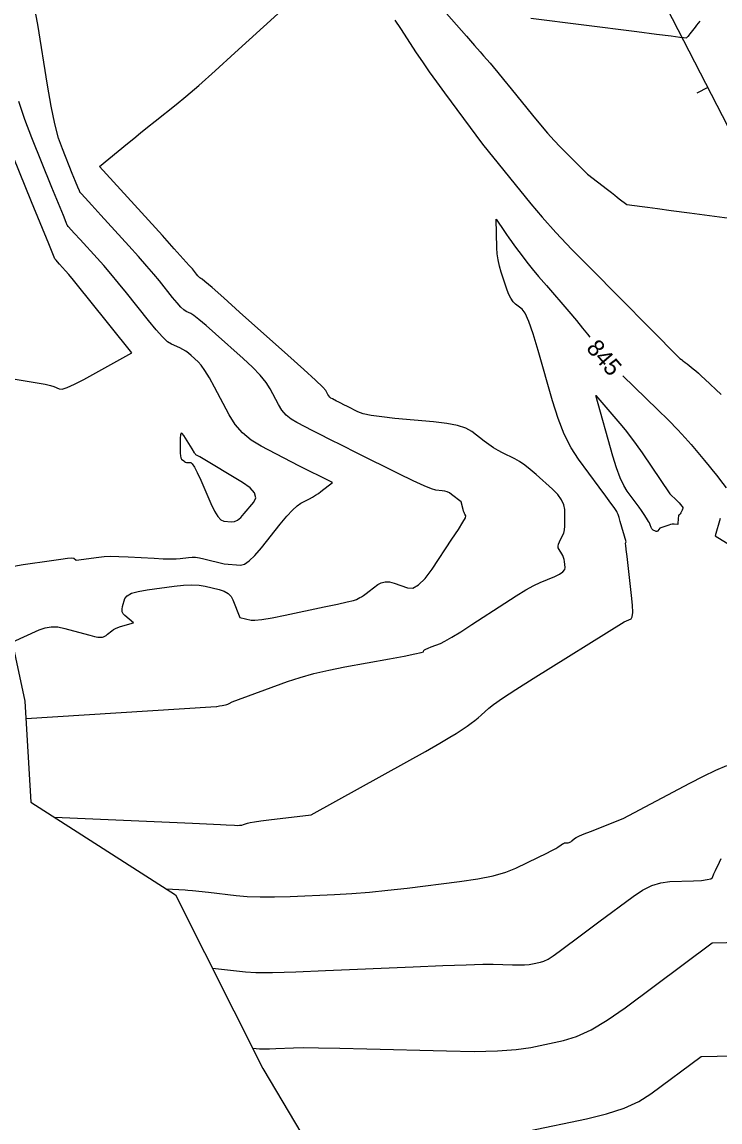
# Model space of a CAD drawing. Extents: x 1715724 to 1716561, y 394063 to 395906.
# Drawn here: x 1715878.2 to 1715935.5, y 395212.3 to 395302.7 of the extents above; entities that cross this region are included whole.
import ezdxf

# ---------------------------------------------------------------- set-up
doc = ezdxf.new("R2010")
doc.units = 0
for name, color, linetype in [('DT_X_Contour_Major', 7, 'Continuous'), ('DT_X_Contour_Minor', 7, 'Continuous'), ('DT_X_TIN_Hull', 7, 'Continuous'), ('GE_P_CL_10', 7, 'Continuous')]:
    doc.layers.add(name, color=color, linetype=linetype)

msp = doc.modelspace()

# ---------------------------------------------------------------- linework, layer by layer
at = {"layer": 'DT_X_Contour_Major'}
for points in [[(1715880.835, 395237.361), (1715892.192, 395236.859), (1715894.484, 395236.754), (1715894.957, 395236.73), (1715895.619, 395236.69), (1715895.852, 395236.683), (1715896.055, 395236.69), (1715896.228, 395236.712), (1715896.37, 395236.748), (1715896.708, 395236.865), (1715896.913, 395236.915), (1715897.271, 395236.976), (1715897.784, 395237.05), (1715898.451, 395237.136), (1715901.926, 395237.565), (1715909.789, 395241.915), (1715911.306, 395242.76), (1715912.486, 395243.428), (1715913.33, 395243.921), (1715913.837, 395244.237), (1715914.74, 395244.847), (1715915.065, 395245.074), (1715915.365, 395245.298), (1715915.638, 395245.519), (1715915.884, 395245.737), (1715916.508, 395246.314), (1715916.912, 395246.629), (1715917.657, 395247.139), (1715918.744, 395247.846), (1715920.171, 395248.748), (1715927.628, 395253.418), (1715928.208, 395253.659), (1715928.303, 395253.817), (1715928.341, 395254.189), (1715928.322, 395254.775), (1715928.245, 395255.575), (1715927.871, 395258.786), (1715927.804, 395259.354), (1715927.762, 395259.697), (1715927.746, 395259.815), (1715927.738, 395259.827), (1715927.737, 395259.834), (1715927.739, 395259.846), (1715927.755, 395259.882), (1715927.811, 395259.988), (1715927.317, 395261.653), (1715927.22, 395261.972), (1715927.139, 395262.218), (1715927.075, 395262.39), (1715927.027, 395262.487), (1715926.922, 395262.649), (1715926.809, 395262.81), (1715926.547, 395263.169), (1715926.137, 395263.728), (1715925.579, 395264.487), (1715923.891, 395266.775), (1715923.283, 395267.719), (1715922.722, 395268.835), (1715922.209, 395270.122), (1715921.744, 395271.581), (1715920.568, 395275.699), (1715920.156, 395277.07), (1715919.802, 395278.094), (1715919.507, 395278.771), (1715919.269, 395279.1), (1715918.713, 395279.516), (1715918.511, 395279.714), (1715918.319, 395279.998), (1715918.138, 395280.367), (1715917.968, 395280.821), (1715917.53, 395282.146), (1715917.385, 395282.643), (1715917.279, 395283.142), (1715917.211, 395283.643), (1715917.182, 395284.146), (1715917.135, 395286.495), (1715917.812, 395285.47), (1715917.972, 395285.234), (1715918.162, 395284.962), (1715918.381, 395284.657), (1715918.631, 395284.316), (1715919.337, 395283.363), (1715919.655, 395282.95), (1715920.079, 395282.426), (1715920.609, 395281.791), (1715921.246, 395281.044), (1715923.086, 395278.905), (1715923.716, 395278.165), (1715924.226, 395277.549), (1715924.616, 395277.056), (1715924.805, 395276.798)], [(1715927.533, 395273.63), (1715930.377, 395270.856), (1715931.274, 395269.969), (1715932.032, 395269.194), (1715932.652, 395268.531), (1715933.133, 395267.98), (1715934.23, 395266.659), (1715934.616, 395266.192), (1715934.952, 395265.781), (1715935.236, 395265.428), (1715935.47, 395265.131), (1715936.025, 395264.415)], [(1715935.525, 395261.909), (1715935.121, 395260.478), (1715936.766, 395259.454)]]:
    msp.add_lwpolyline(points, dxfattribs=at)
at = {"layer": 'DT_X_Contour_Minor'}
for points in [[(1715911.397, 395305.284), (1715913.854, 395302.472), (1715914.685, 395301.521), (1715915.335, 395300.777), (1715915.804, 395300.24), (1715916.093, 395299.91), (1715916.621, 395299.306), (1715916.877, 395299.006), (1715917.25, 395298.557), (1715917.739, 395297.96), (1715918.344, 395297.214), (1715920.114, 395295.029), (1715920.754, 395294.252), (1715921.348, 395293.56), (1715921.894, 395292.953), (1715922.394, 395292.432), (1715924.616, 395290.198), (1715926.262, 395288.929), (1715926.587, 395288.679), (1715926.857, 395288.47), (1715927.072, 395288.304), (1715927.233, 395288.18), (1715927.853, 395287.699), (1715929.12, 395287.537), (1715929.566, 395287.478), (1715930.363, 395287.372), (1715931.511, 395287.219), (1715933.008, 395287.019), (1715940.815, 395285.973)], [(1715878.507, 395245.476), (1715893.7, 395246.43), (1715894.141, 395246.451), (1715894.157, 395246.453), (1715894.192, 395246.459), (1715894.402, 395246.506), (1715894.631, 395246.549), (1715894.903, 395246.596), (1715894.998, 395246.615), (1715895.08, 395246.637), (1715895.149, 395246.662), (1715895.205, 395246.69), (1715895.434, 395246.825), (1715899.992, 395248.494), (1715901.018, 395248.838), (1715902.145, 395249.155), (1715903.37, 395249.446), (1715904.696, 395249.709), (1715908.363, 395250.375), (1715909.569, 395250.598), (1715910.434, 395250.769), (1715910.959, 395250.887), (1715911.144, 395250.953), (1715911.184, 395251.058), (1715911.233, 395251.106), (1715911.349, 395251.171), (1715911.532, 395251.254), (1715911.783, 395251.354), (1715912.541, 395251.643), (1715912.917, 395251.821), (1715913.474, 395252.137), (1715914.213, 395252.592), (1715915.133, 395253.186), (1715917.83, 395254.953), (1715918.771, 395255.556), (1715919.571, 395256.04), (1715920.229, 395256.405), (1715920.747, 395256.65), (1715921.938, 395257.146), (1715922.326, 395257.331), (1715922.597, 395257.516), (1715922.752, 395257.699), (1715922.789, 395257.882), (1715922.732, 395258.369), (1715922.703, 395258.545), (1715922.657, 395258.707), (1715922.595, 395258.857), (1715922.517, 395258.994), (1715922.286, 395259.342), (1715922.223, 395259.48), (1715922.207, 395259.634), (1715922.237, 395259.802), (1715922.314, 395259.985), (1715922.583, 395260.494), (1715922.67, 395260.708), (1715922.731, 395260.97), (1715922.765, 395261.279), (1715922.773, 395261.635), (1715922.757, 395262.648), (1715922.689, 395263.037), (1715922.498, 395263.444), (1715922.184, 395263.87), (1715921.746, 395264.313), (1715920.413, 395265.521), (1715919.929, 395265.94), (1715919.475, 395266.293), (1715919.052, 395266.578), (1715918.659, 395266.797), (1715917.653, 395267.292), (1715917.275, 395267.491), (1715916.896, 395267.717), (1715916.516, 395267.971), (1715916.134, 395268.252), (1715915.115, 395269.038), (1715914.631, 395269.31), (1715913.947, 395269.534), (1715913.06, 395269.712), (1715911.973, 395269.842), (1715908.803, 395270.129), (1715907.722, 395270.243), (1715906.857, 395270.37), (1715906.207, 395270.512), (1715905.773, 395270.667), (1715904.904, 395271.099), (1715904.603, 395271.249), (1715904.353, 395271.374), (1715904.153, 395271.474), (1715904.004, 395271.55), (1715903.674, 395271.72), (1715903.557, 395271.791), (1715903.456, 395271.877), (1715903.369, 395271.977), (1715903.298, 395272.091), (1715903.127, 395272.415), (1715902.885, 395272.687), (1715902.287, 395273.262), (1715901.332, 395274.139), (1715900.022, 395275.318), (1715896.052, 395278.865), (1715894.744, 395280.032), (1715893.796, 395280.871), (1715893.208, 395281.383), (1715892.98, 395281.568), (1715892.854, 395281.625), (1715892.796, 395281.663), (1715892.719, 395281.736), (1715892.623, 395281.842), (1715892.506, 395281.983), (1715892.169, 395282.404), (1715891.921, 395282.694), (1715891.427, 395283.249), (1715890.688, 395284.069), (1715889.705, 395285.153), (1715884.543, 395290.831), (1715886.841, 395292.717), (1715887.352, 395293.135), (1715887.902, 395293.58), (1715888.49, 395294.052), (1715889.117, 395294.551), (1715890.838, 395295.92), (1715891.624, 395296.57), (1715892.69, 395297.492), (1715894.037, 395298.689), (1715895.664, 395300.158), (1715900.376, 395304.441)], [(1715877.367, 395251.733), (1715879.583, 395252.758), (1715880.07, 395252.93), (1715880.584, 395253.007), (1715881.124, 395252.989), (1715881.69, 395252.875), (1715883.235, 395252.445), (1715883.752, 395252.304), (1715884.146, 395252.207), (1715884.414, 395252.151), (1715884.559, 395252.138), (1715884.779, 395252.159), (1715884.868, 395252.179), (1715884.968, 395252.224), (1715885.08, 395252.294), (1715885.204, 395252.39), (1715885.55, 395252.677), (1715885.692, 395252.779), (1715885.859, 395252.87), (1715886.051, 395252.951), (1715886.268, 395253.02), (1715887.336, 395253.321), (1715886.613, 395253.927), (1715886.487, 395254.072), (1715886.417, 395254.245), (1715886.403, 395254.446), (1715886.446, 395254.676), (1715886.637, 395255.329), (1715886.803, 395255.557), (1715887.16, 395255.752), (1715887.708, 395255.914), (1715888.446, 395256.043), (1715890.669, 395256.343), (1715891.453, 395256.427), (1715892.139, 395256.456), (1715892.725, 395256.43), (1715893.214, 395256.347), (1715894.384, 395256.054), (1715894.783, 395255.918), (1715895.104, 395255.732), (1715895.345, 395255.496), (1715895.508, 395255.209), (1715896.082, 395253.753), (1715896.992, 395253.547), (1715897.313, 395253.54), (1715897.887, 395253.607), (1715898.714, 395253.748), (1715899.794, 395253.963), (1715903.01, 395254.635), (1715904.08, 395254.863), (1715904.875, 395255.041), (1715905.396, 395255.17), (1715905.643, 395255.25), (1715905.936, 395255.399), (1715906.066, 395255.473), (1715906.234, 395255.584), (1715906.441, 395255.733), (1715906.686, 395255.919), (1715907.392, 395256.465), (1715907.676, 395256.626), (1715907.995, 395256.7), (1715908.351, 395256.686), (1715908.743, 395256.585), (1715909.837, 395256.201), (1715910.272, 395256.189), (1715910.756, 395256.443), (1715911.29, 395256.962), (1715911.873, 395257.746), (1715913.493, 395260.191), (1715914.021, 395261), (1715914.388, 395261.592), (1715914.595, 395261.967), (1715914.642, 395262.126), (1715914.552, 395262.261), (1715914.519, 395262.322), (1715914.485, 395262.403), (1715914.452, 395262.506), (1715914.418, 395262.63), (1715914.262, 395263.258), (1715913.455, 395263.88), (1715913.278, 395263.999), (1715913.094, 395264.089), (1715912.901, 395264.151), (1715912.701, 395264.183), (1715912.158, 395264.232), (1715911.816, 395264.33), (1715911.2, 395264.584), (1715910.308, 395264.996), (1715909.142, 395265.565), (1715905.665, 395267.292), (1715904.463, 395267.89), (1715903.462, 395268.391), (1715902.663, 395268.793), (1715902.067, 395269.097), (1715900.745, 395269.777), (1715900.279, 395270.061), (1715899.873, 395270.402), (1715899.527, 395270.802), (1715899.241, 395271.259), (1715898.558, 395272.555), (1715898.227, 395273.075), (1715897.747, 395273.665), (1715897.118, 395274.323), (1715896.34, 395275.05), (1715894.067, 395277.082), (1715893.302, 395277.757), (1715892.712, 395278.258), (1715892.298, 395278.587), (1715892.058, 395278.741), (1715891.653, 395278.923), (1715891.469, 395279.046), (1715891.223, 395279.278), (1715890.913, 395279.62), (1715890.541, 395280.07), (1715889.463, 395281.418), (1715889.003, 395281.978), (1715888.429, 395282.647), (1715887.741, 395283.426), (1715886.94, 395284.315), (1715884.653, 395286.831), (1715883.902, 395287.657), (1715883.365, 395288.248), (1715883.042, 395288.605), (1715882.933, 395288.727), (1715882.928, 395288.74), (1715882.888, 395288.838), (1715882.772, 395289.124), (1715882.579, 395289.596), (1715882.311, 395290.255), (1715881.492, 395292.262), (1715881.186, 395293.154), (1715880.881, 395294.325), (1715880.576, 395295.776), (1715880.273, 395297.504), (1715879.465, 395302.487), (1715879.157, 395304.187)], [(1715908.802, 395302.84), (1715909.257, 395302.151), (1715910.561, 395300.176), (1715911.072, 395299.416), (1715911.629, 395298.614), (1715912.231, 395297.771), (1715912.878, 395296.887), (1715916.003, 395292.666), (1715919.97, 395287.768), (1715920.911, 395286.651), (1715922.036, 395285.398), (1715923.344, 395284.01), (1715924.835, 395282.486), (1715932.221, 395275.06), (1715932.334, 395274.973), (1715932.356, 395274.956), (1715932.373, 395274.943), (1715932.386, 395274.932), (1715932.394, 395274.926), (1715932.409, 395274.912), (1715932.438, 395274.888), (1715932.514, 395274.828), (1715932.635, 395274.731), (1715932.804, 395274.598), (1715933.314, 395274.193), (1715933.518, 395274.027), (1715933.746, 395273.83), (1715933.997, 395273.603), (1715934.273, 395273.347), (1715935.617, 395272.081)], [(1715919.978, 395303.025), (1715928.666, 395301.91), (1715930.302, 395301.7), (1715931.486, 395301.548), (1715932.219, 395301.454), (1715932.499, 395301.418), (1715932.754, 395301.383), (1715932.872, 395301.501), (1715932.909, 395301.542), (1715932.97, 395301.617), (1715933.055, 395301.725), (1715933.164, 395301.865), (1715933.485, 395302.283), (1715933.608, 395302.443), (1715933.735, 395302.606), (1715933.868, 395302.774)], [(1715877.504, 395257.995), (1715878.277, 395258.108), (1715880.599, 395258.461), (1715881.366, 395258.571), (1715881.927, 395258.639), (1715882.281, 395258.665), (1715882.427, 395258.648), (1715882.63, 395258.469), (1715884.486, 395258.736), (1715884.935, 395258.78), (1715885.484, 395258.798), (1715886.135, 395258.79), (1715886.887, 395258.757), (1715889.027, 395258.633), (1715889.762, 395258.596), (1715890.363, 395258.581), (1715890.829, 395258.586), (1715891.161, 395258.611), (1715891.866, 395258.706), (1715892.142, 395258.726), (1715892.441, 395258.715), (1715892.763, 395258.672), (1715893.108, 395258.598), (1715894.772, 395258.181), (1715896.123, 395258.08), (1715896.448, 395258.152), (1715896.845, 395258.412), (1715897.313, 395258.859), (1715897.853, 395259.494), (1715899.388, 395261.436), (1715899.925, 395262.091), (1715900.386, 395262.597), (1715900.769, 395262.955), (1715901.076, 395263.164), (1715901.791, 395263.526), (1715902.051, 395263.664), (1715902.295, 395263.807), (1715902.523, 395263.957), (1715902.735, 395264.111), (1715903.686, 395264.846), (1715902.41, 395265.48), (1715902.063, 395265.655), (1715900.922, 395266.237), (1715897.816, 395267.834), (1715897.001, 395268.33), (1715896.291, 395268.928), (1715895.685, 395269.627), (1715895.184, 395270.427), (1715893.988, 395272.695), (1715893.569, 395273.463), (1715893.207, 395274.067), (1715892.904, 395274.507), (1715892.659, 395274.783), (1715892.082, 395275.298), (1715891.86, 395275.482), (1715891.629, 395275.646), (1715891.387, 395275.79), (1715891.136, 395275.915), (1715890.452, 395276.222), (1715890.142, 395276.429), (1715889.727, 395276.821), (1715889.204, 395277.397), (1715888.576, 395278.158), (1715886.758, 395280.431), (1715886.096, 395281.249), (1715885.474, 395281.997), (1715884.892, 395282.676), (1715884.35, 395283.285), (1715882.958, 395284.816), (1715882.5, 395285.32), (1715881.974, 395285.904), (1715881.906, 395285.984), (1715881.895, 395286.01), (1715881.813, 395286.21), (1715881.577, 395286.79), (1715880.64, 395289.09), (1715878.977, 395293.169), (1715878.403, 395294.683), (1715877.928, 395296.166)], [(1715875.273, 395273.734), (1715878.607, 395273.193), (1715879.436, 395273.053), (1715880.075, 395272.931), (1715880.525, 395272.828), (1715880.786, 395272.743), (1715881.228, 395272.542), (1715881.479, 395272.534), (1715881.9, 395272.663), (1715882.49, 395272.928), (1715883.25, 395273.329), (1715887.191, 395275.518), (1715883.65, 395279.947), (1715882.963, 395280.803), (1715882.419, 395281.473), (1715882.018, 395281.957), (1715881.76, 395282.255), (1715881.263, 395282.801), (1715881.099, 395282.983), (1715880.98, 395283.116), (1715880.906, 395283.203), (1715880.878, 395283.241), (1715880.382, 395284.457), (1715878.969, 395287.925), (1715876.461, 395294.077)], [(1715925.302, 395271.997), (1715927.278, 395269.701), (1715927.709, 395269.181), (1715928.158, 395268.605), (1715928.623, 395267.972), (1715929.105, 395267.284), (1715931.392, 395263.94), (1715931.955, 395263.39), (1715932.034, 395263.309), (1715932.099, 395263.24), (1715932.149, 395263.182), (1715932.368, 395262.917), (1715932.392, 395262.886), (1715932.45, 395262.811), (1715932.463, 395262.776), (1715932.459, 395262.728), (1715932.439, 395262.665), (1715932.401, 395262.588), (1715932.279, 395262.364), (1715932.237, 395262.291), (1715932.203, 395262.239), (1715932.179, 395262.208), (1715932.162, 395262.199), (1715932.129, 395262.202), (1715932.117, 395262.188), (1715932.105, 395262.143), (1715932.095, 395262.068), (1715932.085, 395261.963), (1715932.04, 395261.402), (1715931.749, 395261.445), (1715931.675, 395261.447), (1715931.576, 395261.433), (1715931.453, 395261.403), (1715931.306, 395261.358), (1715930.563, 395261.111), (1715930.416, 395260.882), (1715930.38, 395260.843), (1715930.334, 395260.826), (1715930.278, 395260.829), (1715930.213, 395260.854), (1715930.027, 395260.949), (1715929.963, 395260.99), (1715929.911, 395261.04), (1715929.871, 395261.1), (1715929.842, 395261.171), (1715929.783, 395261.372), (1715929.752, 395261.455), (1715929.705, 395261.553), (1715929.642, 395261.666), (1715929.563, 395261.794), (1715929.329, 395262.155), (1715929.218, 395262.321), (1715929.061, 395262.545), (1715928.856, 395262.828), (1715927.876, 395264.16), (1715927.598, 395264.618), (1715927.313, 395265.249), (1715927.02, 395266.054), (1715926.72, 395267.031), (1715925.302, 395271.997)], [(1715892.519, 395267.109), (1715892.466, 395267.142), (1715892.418, 395267.186), (1715892.374, 395267.241), (1715892.334, 395267.307), (1715892.16, 395267.636), (1715891.47, 395268.722), (1715891.34, 395268.883), (1715891.247, 395268.899), (1715891.19, 395268.772), (1715891.169, 395268.5), (1715891.163, 395267.583), (1715891.169, 395267.275), (1715891.192, 395267.039), (1715891.232, 395266.874), (1715891.29, 395266.781), (1715891.467, 395266.628), (1715891.537, 395266.577), (1715891.615, 395266.539), (1715891.699, 395266.515), (1715891.791, 395266.504), (1715892.045, 395266.493), (1715892.167, 395266.399), (1715892.342, 395266.128), (1715892.571, 395265.679), (1715892.853, 395265.051), (1715893.677, 395263.141), (1715893.977, 395262.513), (1715894.257, 395262.058), (1715894.519, 395261.779), (1715894.762, 395261.674), (1715895.384, 395261.626), (1715895.625, 395261.655), (1715895.881, 395261.777), (1715896.152, 395261.991), (1715896.439, 395262.299), (1715897.222, 395263.243), (1715897.384, 395263.609), (1715897.285, 395264.001), (1715896.923, 395264.417), (1715896.299, 395264.859), (1715892.775, 395266.977), (1715892.519, 395267.109)], [(1715890.021, 395231.468), (1715891.055, 395231.422), (1715891.586, 395231.391), (1715891.787, 395231.373), (1715892.174, 395231.333), (1715893.503, 395231.184), (1715895.771, 395230.925), (1715896.685, 395230.847), (1715897.73, 395230.809), (1715898.904, 395230.81), (1715900.208, 395230.851), (1715903.858, 395231.01), (1715905.257, 395231.088), (1715906.717, 395231.202), (1715908.238, 395231.351), (1715909.821, 395231.536), (1715914.123, 395232.077), (1715915.621, 395232.297), (1715916.89, 395232.551), (1715917.93, 395232.839), (1715918.741, 395233.16), (1715920.596, 395234.064), (1715921.218, 395234.37), (1715921.691, 395234.61), (1715922.016, 395234.784), (1715922.191, 395234.893), (1715922.462, 395235.095), (1715922.561, 395235.161), (1715922.654, 395235.21), (1715922.74, 395235.24), (1715922.821, 395235.252), (1715923.029, 395235.259), (1715923.107, 395235.27), (1715923.185, 395235.298), (1715923.264, 395235.344), (1715923.343, 395235.406), (1715923.554, 395235.594), (1715923.696, 395235.684), (1715923.961, 395235.814), (1715924.35, 395235.983), (1715924.863, 395236.191), (1715927.548, 395237.255), (1715933.043, 395240.154), (1715934.164, 395240.73), (1715935.173, 395241.217), (1715936.069, 395241.615)], [(1715893.821, 395224.955), (1715896.53, 395224.646), (1715897.376, 395224.602), (1715898.753, 395224.605), (1715900.66, 395224.655), (1715903.098, 395224.75), (1715910.306, 395225.066), (1715912.745, 395225.167), (1715914.655, 395225.236), (1715916.036, 395225.27), (1715916.889, 395225.271), (1715918.458, 395225.229), (1715919.003, 395225.221), (1715919.461, 395225.23), (1715919.832, 395225.256), (1715920.116, 395225.298), (1715920.758, 395225.433), (1715921.034, 395225.526), (1715921.382, 395225.704), (1715921.801, 395225.968), (1715922.291, 395226.317), (1715924.249, 395227.777), (1715925.553, 395228.748), (1715928.376, 395230.85), (1715929.148, 395231.361), (1715929.908, 395231.733), (1715930.655, 395231.966), (1715931.39, 395232.062), (1715933.334, 395232.131), (1715933.978, 395232.167), (1715934.451, 395232.225), (1715934.754, 395232.304), (1715934.886, 395232.405), (1715935.011, 395232.701), (1715935.065, 395232.826), (1715935.135, 395232.978), (1715935.219, 395233.158), (1715935.318, 395233.364), (1715935.602, 395233.951)], [(1715897.124, 395218.385), (1715897.676, 395218.322), (1715897.848, 395218.314), (1715898.128, 395218.314), (1715898.516, 395218.324), (1715899.013, 395218.344), (1715900.48, 395218.408), (1715901.268, 395218.421), (1715902.534, 395218.411), (1715904.275, 395218.379), (1715906.493, 395218.324), (1715913.043, 395218.148), (1715915.318, 395218.116), (1715917.23, 395218.154), (1715918.779, 395218.261), (1715919.966, 395218.437), (1715922.646, 395218.998), (1715923.717, 395219.325), (1715924.919, 395219.885), (1715926.253, 395220.677), (1715927.718, 395221.702), (1715934.862, 395227.029), (1715937.215, 395227.077)], [(1715919.816, 395211.576), (1715924.534, 395212.564), (1715926.193, 395212.971), (1715927.63, 395213.45), (1715928.846, 395214.001), (1715929.84, 395214.623), (1715933.965, 395217.698), (1715944.537, 395217.914), (1715946.582, 395217.98), (1715948.188, 395218.086), (1715949.353, 395218.233), (1715950.079, 395218.419), (1715952.437, 395219.384), (1715955.696, 395215.837), (1715956.548, 395214.903), (1715958.008, 395213.279), (1715958.221, 395213.042), (1715958.561, 395212.667), (1715960.094, 395210.953)]]:
    msp.add_lwpolyline(points, dxfattribs=at)
at = {"layer": 'DT_X_TIN_Hull'}
msp.add_lwpolyline([(1715850.028, 395441.188), (1715860.985, 395418.75), (1715840.343, 395413.155), (1715827.717, 395391.508), (1715839.699, 395364.437), (1715852.11, 395336.438), (1715855.181, 395321.871), (1715858.501, 395310.841), (1715855.162, 395309.042), (1715867.954, 395284.03), (1715876.157, 395257.285), (1715878.423, 395246.892), (1715878.914, 395238.593), (1715890.796, 395230.971), (1715897.968, 395216.706), (1715912.084, 395192.899)], dxfattribs=at)
at = {"layer": 'GE_P_CL_10'}
for p, q in [((1716249.46, 394685.42), (1715852.538, 395456.564)), ((1715934.509, 395297.312), (1715933.619, 395296.854))]:
    msp.add_line(p, q, dxfattribs=at)

# ---------------------------------------------------------------- texts
at = {"layer": 'DT_X_Contour_Major'}
msp.add_text('845', height=1.4, rotation=310.72575, dxfattribs=at).set_placement((1715924.456, 395275.85))

doc.saveas('drawing.dxf')
